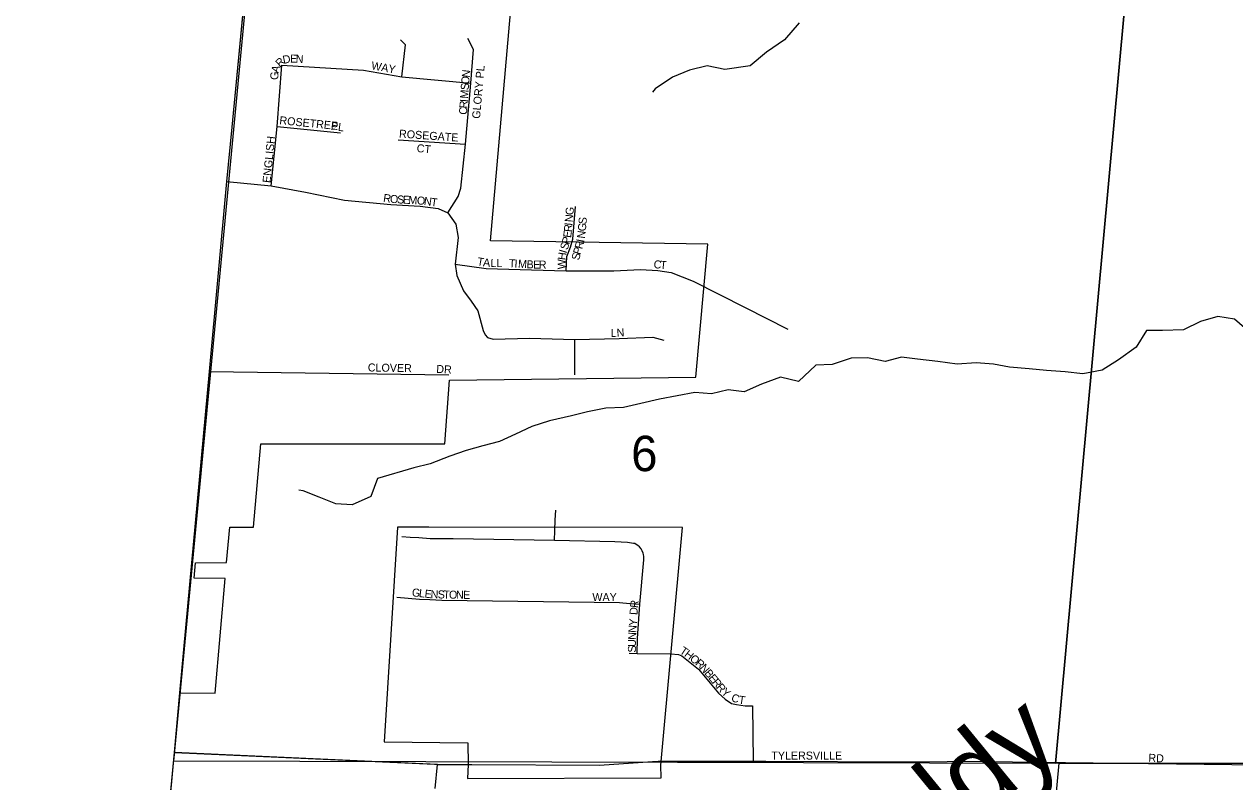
# Model space of a CAD drawing. Extents: x 0 to 1064, y 0 to 440.
# Drawn here: x 117.84 to 140.76, y 149.51 to 163.84 of the extents above; entities that cross this region are included whole.
import ezdxf

# ---------------------------------------------------------------- set-up
doc = ezdxf.new("R2010")
doc.units = 0
for name, color, linetype in [('GM_X_City_Street', 7, 'Continuous'), ('GM_X_City_Street_Text', 7, 'Continuous'), ('GM_X_Corporation', 7, 'Continuous'), ('GM_X_County', 7, 'Continuous'), ('GM_X_County_Road', 7, 'Continuous'), ('GM_X_Minor_River', 7, 'Continuous'), ('GM_X_Minor_River_Text', 7, 'Continuous'), ('GM_X_Section', 7, 'Continuous'), ('GM_X_Section_Text', 7, 'Continuous'), ('GM_X_Township_Subdivision', 7, 'Continuous'), ('GM_X_Township_Subdivision_Text', 7, 'Continuous')]:
    doc.layers.add(name, color=color, linetype=linetype)

msp = doc.modelspace()

# ---------------------------------------------------------------- linework, layer by layer
at = {"layer": 'GM_X_City_Street'}
for points in [[(130.084, 151.929), (130.226, 151.912), (130.291, 151.886), (130.606, 151.636), (130.981, 151.183), (131.107, 151.066), (131.227, 150.984), (131.327, 150.967), (131.49, 150.941), (131.624, 150.941), (131.641, 149.894)], [(129.735, 149.887), (129.84, 149.894), (131.641, 149.894), (131.882, 149.894), (134.602, 149.885), (135.314, 149.892)], [(135.314, 149.892), (135.547, 149.894), (137.553, 149.867), (141.223, 149.823)], [(125.605, 149.836), (125.667, 149.834), (126.241, 149.831)]]:
    msp.add_lwpolyline(points, dxfattribs=at)
at = {"layer": 'GM_X_Corporation'}
msp.add_lwpolyline([(125.617, 149.375), (125.667, 149.834), (120.683, 150.061), (120.786, 151.187), (121.455, 151.182), (121.645, 153.353), (121.057, 153.357), (121.082, 153.651), (121.671, 153.655), (121.73, 154.321), (122.184, 154.321), (122.323, 155.902), (125.804, 155.902), (125.892, 157.106), (130.555, 157.163), (130.782, 159.683), (126.668, 159.745), (127.109, 164.783)], dxfattribs=at)
msp.add_lwpolyline([(125.503, 154.326), (124.91, 154.326), (124.655, 150.258), (126.238, 150.245), (126.245, 149.831), (126.234, 149.565), (129.895, 149.578), (129.894, 149.817), (130.299, 154.317)], close=True, dxfattribs=at)
at = {"layer": 'GM_X_County'}
msp.add_lwpolyline([(117.841, 119.378), (118.767, 128.909), (118.856, 130.044), (119.18, 133.83), (119.339, 135.631), (119.47, 136.982), (119.739, 139.645), (119.895, 141.452), (120.056, 143.221), (120.683, 150.061), (120.786, 151.187), (121.346, 157.269), (121.677, 160.868), (121.775, 161.892), (122.193, 166.235), (122.368, 168.166), (122.612, 170.544), (122.865, 172.827), (122.88, 172.966), (123.415, 177.582)], dxfattribs=at)
at = {"layer": 'GM_X_County_Road'}
for points in [[(120.784, 151.158), (120.786, 151.187), (121.346, 157.269), (121.677, 160.868), (121.775, 161.892), (122.189, 166.192)], [(120.683, 150.061), (120.784, 151.158)], [(120.58, 148.939), (120.683, 150.061)], [(120.683, 150.061), (125.605, 149.836)], [(126.241, 149.831), (126.311, 149.83), (128.729, 149.817), (129.735, 149.887)]]:
    msp.add_lwpolyline(points, dxfattribs=at)
at = {"layer": 'GM_X_Minor_River'}
for points in [[(132.509, 163.868), (132.23, 163.546), (131.889, 163.316), (131.585, 163.054), (131.105, 162.988), (130.771, 163.054), (130.436, 162.976), (130.114, 162.842), (129.786, 162.617), (129.731, 162.556)], [(141.088, 157.971), (140.753, 158.262), (140.437, 158.311), (140.109, 158.214), (139.787, 158.056), (139.391, 158.043), (139.087, 158.049), (138.887, 157.728), (138.552, 157.491), (138.248, 157.296), (137.878, 157.229), (137.543, 157.266), (137.19, 157.29), (136.862, 157.321), (136.491, 157.351), (136.187, 157.412), (135.859, 157.436), (135.5, 157.406), (135.136, 157.46), (134.752, 157.503), (134.448, 157.539), (134.138, 157.46), (133.804, 157.527), (133.494, 157.521), (133.135, 157.4), (132.825, 157.387), (132.497, 157.078), (132.156, 157.163), (131.798, 157.029), (131.469, 156.883), (131.165, 156.92), (130.849, 156.847), (130.533, 156.871), (130.199, 156.81), (129.864, 156.744), (129.511, 156.665), (129.183, 156.586), (128.849, 156.573), (128.502, 156.507), (128.198, 156.428), (127.785, 156.337), (127.45, 156.227), (127.14, 156.081), (126.836, 155.948), (126.52, 155.863), (126.204, 155.772), (125.9, 155.668), (125.523, 155.523), (125.213, 155.45), (124.526, 155.243), (124.404, 154.903), (124.051, 154.745), (123.741, 154.763), (123.425, 154.891), (123.121, 155.012), (123.042, 155.025)]]:
    msp.add_lwpolyline(points, dxfattribs=at)
at = {"layer": 'GM_X_Section'}
for points in [[(122.397, 168.034), (138.483, 166.315), (138.864, 166.277), (137.363, 149.854), (120.675, 149.894)], [(138.864, 166.277), (154.714, 164.637), (153.404, 149.84), (137.43, 149.859), (137.363, 149.854)], [(153.404, 149.84), (153.371, 149.447), (151.892, 133.436), (135.935, 133.672), (137.43, 149.859)]]:
    msp.add_lwpolyline(points, close=True, dxfattribs=at)
at = {"layer": 'GM_X_Township_Subdivision'}
for points in [[(124.992, 162.848), (125.061, 163.453), (124.966, 163.548)], [(125.861, 160.271), (126.053, 160.579), (126.104, 160.743), (126.191, 161.575), (126.296, 162.724), (126.348, 163.364), (126.239, 163.571)], [(122.514, 160.786), (122.631, 161.905), (122.718, 163.066), (124.264, 162.972), (124.992, 162.848), (126.296, 162.724)], [(122.631, 161.905), (123.831, 161.788)], [(124.922, 161.657), (126.191, 161.575)], [(121.677, 160.868), (122.514, 160.786), (123.163, 160.663), (123.901, 160.514), (124.779, 160.43), (125.339, 160.402), (125.675, 160.355), (125.861, 160.271), (126.011, 160.057), (126.057, 159.805), (126.001, 159.3), (126.029, 159.086), (126.157, 158.799), (126.302, 158.601), (126.426, 158.418), (126.53, 158.045), (126.567, 157.962), (126.613, 157.912), (126.719, 157.885), (127.405, 157.903), (128.263, 157.875), (129.104, 157.895), (129.739, 157.922), (129.95, 157.864)], [(128.097, 159.175), (128.111, 159.445), (128.181, 159.622), (128.223, 159.776), (128.275, 160.393)], [(126.001, 159.3), (126.585, 159.221), (127.444, 159.193), (128.097, 159.175), (129.003, 159.174), (129.507, 159.202), (129.834, 159.184), (130.086, 159.146), (130.506, 158.978), (131.486, 158.484), (132.298, 158.073)], [(128.261, 157.207), (128.263, 157.875)], [(121.346, 157.269), (125.88, 157.209)], [(127.881, 154.07), (127.883, 154.262), (127.89, 154.454), (127.903, 154.645)], [(129.443, 151.934), (129.447, 152.214), (129.492, 152.869), (129.57, 153.705), (129.57, 153.77), (129.564, 153.805), (129.557, 153.835), (129.539, 153.876), (129.518, 153.914), (129.486, 153.949), (129.459, 153.975), (129.425, 153.998), (129.399, 154.012), (129.374, 154.017), (129.258, 154.032), (129.141, 154.041), (129.023, 154.045), (127.881, 154.07), (125.962, 154.101), (125.744, 154.1), (125.526, 154.106), (125.309, 154.119), (125.148, 154.13), (124.986, 154.144)], [(124.897, 153), (125.326, 152.964), (125.518, 152.953), (125.744, 152.945), (129.112, 152.898), (129.302, 152.881), (129.492, 152.869)], [(129.294, 151.94), (129.443, 151.934), (130.084, 151.929)]]:
    msp.add_lwpolyline(points, dxfattribs=at)

# ---------------------------------------------------------------- texts
at = {"layer": 'GM_X_City_Street_Text'}
for s, height, rotation, p in [('T', 0.152, 326.4767, (130.236, 151.949)), ('H', 0.152, 322.2515, (130.323, 151.891)), ('O', 0.152, 321.4426, (130.428, 151.81)), ('R', 0.152, 319.8991, (130.531, 151.728)), ('N', 0.152, 311.9693, (130.619, 151.654)), ('B', 0.152, 309.7558, (130.707, 151.556)), ('E', 0.152, 309.7181, (130.784, 151.464)), ('R', 0.152, 309.7018, (130.852, 151.382)), ('R', 0.152, 310.5305, (130.93, 151.288)), ('Y', 0.152, 318.6683, (131.025, 151.18)), ('C', 0.152, 339.6218, (131.21, 151.039)), ('T', 0.152, 351.114, (131.354, 150.988)), ('TYLERSVILLE', 0.15152, 0, (131.983, 149.925)), ('RD', 0.1515, 356.9769, (139.118, 149.885))]:
    msp.add_text(s, height=height, rotation=rotation, dxfattribs=at).set_placement(p)
at = {"layer": 'GM_X_Minor_River_Text'}
msp.add_text('Muddy', height=1.5151, rotation=39.3233, dxfattribs=at).set_placement((132.831, 146.249))
at = {"layer": 'GM_X_Section_Text'}
msp.add_text('6', height=0.67, rotation=0, dxfattribs=at).set_placement((129.33, 155.384))
at = {"layer": 'GM_X_Township_Subdivision_Text'}
for s, height, rotation, p in [('R', 0.152, 42.5327, (122.681, 163.02)), ('D', 0.152, 12.361, (122.751, 163.091)), ('E', 0.152, 357.2752, (122.871, 163.119)), ('N', 0.152, 357.2752, (122.977, 163.114)), ('G', 0.152, 87.7903, (122.649, 162.787)), ('A', 0.152, 72.7044, (122.652, 162.91)), ('WAY', 0.1515, 349.6934, (124.402, 162.991)), ('N', 0.152, 83.6936, (126.273, 162.828)), ('GLORY PL', 0.1515, 84.9604, (126.468, 162.049)), ('S', 0.152, 85.9806, (126.253, 162.591)), ('O', 0.152, 84.4177, (126.26, 162.696)), ('M', 0.152, 86.1744, (126.242, 162.431)), ('C', 0.152, 86.1601, (126.221, 162.125)), ('R', 0.152, 86.1882, (126.229, 162.245)), ('I', 0.152, 86.151, (126.237, 162.365)), ('ROSETREE', 0.1515, 354.2894, (122.666, 161.952)), ('PL', 0.1515, 352.3949, (123.64, 161.845)), ('ROSEGATE', 0.1515, 356.081, (124.932, 161.698)), ('ENGLISH', 0.1515, 84.193, (122.501, 160.833)), ('CT', 0.1515, 353.6638, (125.264, 161.426)), ('R', 0.152, 351.0526, (124.628, 160.485)), ('O', 0.152, 355.2514, (124.759, 160.465)), ('S', 0.152, 357.1757, (124.897, 160.453)), ('E', 0.152, 357.2145, (125.004, 160.448)), ('M', 0.152, 357.2304, (125.11, 160.443)), ('O', 0.152, 355.2745, (125.269, 160.435)), ('N', 0.152, 352.7015, (125.4, 160.424)), ('T', 0.152, 352.5768, (125.532, 160.407)), ('N', 0.152, 84.7917, (128.223, 160.091)), ('G', 0.152, 84.8005, (128.235, 160.224)), ('S', 0.152, 84.6298, (128.482, 160.051)), ('R', 0.152, 84.7328, (128.206, 159.905)), ('I', 0.152, 84.8065, (128.217, 160.024)), ('G', 0.152, 84.3721, (128.469, 159.918)), ('P', 0.152, 74.1332, (128.157, 159.666)), ('E', 0.152, 82.5137, (128.191, 159.793)), ('R', 0.152, 74.4742, (128.402, 159.576)), ('I', 0.152, 79.663, (128.438, 159.706)), ('N', 0.152, 82.621, (128.451, 159.78)), ('H', 0.152, 82.3923, (128.089, 159.371)), ('I', 0.152, 73.0579, (128.105, 159.497)), ('S', 0.152, 72.628, (128.124, 159.56)), ('S', 0.152, 78.1381, (128.348, 159.368)), ('P', 0.152, 72.4895, (128.369, 159.469)), ('T', 0.152, 349.9264, (126.405, 159.284)), ('A', 0.152, 353.9558, (126.521, 159.264)), ('L', 0.152, 357.9853, (126.665, 159.249)), ('L', 0.152, 0, (126.778, 159.245)), ('T', 0.152, 356.5549, (127.012, 159.245)), ('I', 0.152, 356.5437, (127.118, 159.239)), ('M', 0.152, 356.5666, (127.185, 159.235)), ('B', 0.152, 357.4088, (127.347, 159.225)), ('E', 0.152, 359.5489, (127.473, 159.219)), ('R', 0.152, 359.9687, (127.581, 159.218)), ('W', 0.152, 89.6637, (128.088, 159.203)), ('C', 0.152, 352.8659, (129.748, 159.231)), ('T', 0.152, 354.4776, (129.872, 159.216)), ('L', 0.152, 0.8196, (128.944, 157.925)), ('N', 0.152, 4.2485, (129.06, 157.927)), ('CLOVER', 0.1515, 358.9775, (124.344, 157.272)), ('DR', 0.1515, 356.8222, (125.638, 157.245)), ('G', 0.152, 353.4957, (125.173, 153.018)), ('L', 0.152, 353.5103, (125.306, 153.003)), ('E', 0.152, 354.5559, (125.415, 152.991)), ('N', 0.152, 358.2926, (125.532, 152.98)), ('S', 0.152, 359.0528, (125.667, 152.976)), ('T', 0.152, 359.0438, (125.774, 152.974)), ('O', 0.152, 359.0469, (125.88, 152.972)), ('N', 0.152, 359.0694, (126.014, 152.97)), ('E', 0.152, 359.0438, (126.147, 152.968)), ('WAY', 0.1515, 0, (128.596, 152.925)), ('R', 0.152, 82.3748, (129.457, 152.788)), ('D', 0.152, 85.8209, (129.448, 152.658)), ('N', 0.152, 86.0841, (129.428, 152.32)), ('Y', 0.152, 86.0623, (129.438, 152.453)), ('U', 0.152, 89.6721, (129.421, 152.056)), ('N', 0.152, 87.2446, (129.422, 152.188)), ('S', 0.152, 89.9453, (129.421, 151.95))]:
    msp.add_text(s, height=height, rotation=rotation, dxfattribs=at).set_placement(p)

doc.saveas('drawing.dxf')
